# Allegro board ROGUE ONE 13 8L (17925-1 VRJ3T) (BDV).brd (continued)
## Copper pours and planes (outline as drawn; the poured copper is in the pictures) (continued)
3D3V_S0 on BOTTOM: 73.7,22.24 73.57,22.37 73.57,22.88 73.45,23.01 72.81,23.01 72.68,23.13 72.68,24.28 72.81,24.4 72.81,24.66 73.7,25.55 76.49,25.55 76.87,25.16 76.87,23.64 76.75,23.51 75.6,23.51 75.35,23.26 75.35,22.37 75.22,22.24
3D3V_S0 on BOTTOM: 166.03,38.88 165.9,39.01 165.9,39.64 166.03,39.77 166.66,39.77 166.92,40.02 166.92,40.79 167.17,40.79 167.17,39.77 167.3,39.64 167.3,39.26 166.92,38.88
3D3V_S0 on BOTTOM: 187.36,89.17 187.01,89.53 186.53,89.53 186.35,89.71 186.35,91.2 186.48,91.33 187.24,91.33 187.36,91.46 188.51,91.46 188.63,91.33 188.63,89.81 188,89.17 ; 1 cut-out
3D3V_S0 on L3SGND: 190.16,5.99 189.02,4.84 185.08,4.84 183.43,6.5 181.14,6.5 176.95,2.3 163.11,2.3 161.84,3.57 160.06,3.57 159.04,2.56 143.04,2.56 142.28,3.32 142.28,6.37 144.06,8.15 170.6,8.15 170.98,8.53 178.86,8.53 179.36,9.04 183.55,9.04 184.32,9.8 187.24,9.8 190.16,6.88 ; 1 cut-out
3D3V_S0 on L3SGND: 182.54,66.82 181.01,66.82 179.62,65.42 179.62,64.41 180,64.03 181.01,64.03 182.67,65.68 182.67,66.69
3D3V_S0 on L3SGND: 141.77,102.51 141.77,100.98 145.07,97.68 145.58,97.68 152.19,91.08 155.61,91.08 159.93,86.76 159.93,85.49 160.44,84.98 161.08,84.98 161.58,85.49 161.58,86 162.09,86.51 162.09,88.41 156.76,93.74 152.19,93.74 145.33,100.6 145.33,102 144.57,102.76 142.03,102.76
3D3V_S0 on L3SGND: 144.44,21.86 145.96,21.86 147.74,23.64 147.74,24.02 148.25,24.53 155.23,24.53 159.68,28.97 159.68,36.98 161.35,38.65 161.35,39.16 161.25,39.26 160.57,39.26 160.44,39.39 160.44,40.28 161.84,41.67 161.84,48.02 167.55,53.74 167.55,57.93 170.98,61.36 172.25,61.36 173.39,62.5 173.39,64.66 173.01,65.04 169.97,65.04 166.41,61.49 166.41,60.6 164.25,58.44 164.25,55.01 161.27,52.02 159.11,52.02 156.63,49.55 156.63,32.28 156.12,31.77 156.12,28.59 155.49,27.96 148.88,27.96 143.93,23.01 143.93,22.37 ; 1 cut-out
3D3V_S0 on L4SGND: 160.72,39.26 165.44,39.26 165.95,39.77 166.43,39.77 166.64,39.57 166.64,38.91 165.85,38.12 160.92,38.12 160.54,38.5 160.54,39.08
3D3V_S0 on L4SGND: 72.43,26.56 72.43,24.53 73.45,23.51 73.45,22.37 74.08,21.74 81.19,21.74 82.08,22.62 96.18,22.62 96.81,23.26 100.24,23.26 103.8,19.7 110.66,19.7 111.93,20.97 122.85,20.97 123.23,20.59 129.07,20.59 130.09,21.61 130.09,23.26 125.13,28.21 74.08,28.21
3D3V_S0 on L4SGND: 171.74,65.42 171.36,65.04 171.36,63.65 172.12,62.88 180.51,62.88 181.78,64.15 181.78,65.68 181.52,65.93 179.87,65.93 179.36,65.42
3D3V_S5 on TOP: 31.28,18.43 30.82,18.89 30.82,21.2 30.98,21.35 32.04,21.35 32.17,21.23 32.17,18.81 31.79,18.43
3D3V_S5 on TOP: 77.76,4.08 72.18,9.67 72.18,17.67 72.56,18.05 72.56,19.7 72.94,20.08 72.94,20.72 73.06,20.85 74.59,20.85 75.1,20.34 75.1,13.48 76.49,12.08 76.49,10.81 76.75,10.56 79.03,10.56 79.41,10.18 79.41,8.65 80.56,7.51 81.32,7.51 81.83,7 91.86,7 92.37,7.51 94.27,7.51 94.78,8.02 108.75,8.02 110.02,9.29 110.02,11.32 109.51,11.83 109.51,21.99 112.05,24.53 115.74,24.53 116.12,24.15 116.12,22.5 115.86,22.24 115.86,21.74 115.61,21.48 113.96,21.48 112.56,20.08 112.56,11.98 113.13,11.41 128.08,11.41 131.04,8.45 133.59,8.45 134.28,7.77 134.28,5.17 133.8,4.69 130.24,4.69 127.03,7.9 114.83,7.9 111.01,4.08 ; 16 cut-outs
3D3V_S5 on TOP: 170.98,49.17 170.6,49.55 170.6,56.79 173.52,59.71 173.52,64.92 173.14,65.3 169.2,65.3 168.82,65.68 168.82,66.95 168.95,67.07 170.22,67.07 170.73,67.58 171.36,67.58 171.36,66.95 171.49,66.82 172.25,66.82 172.38,66.95 172.38,68.47 172.51,68.6 173.27,68.6 173.52,68.34 175.05,68.34 175.3,68.6 176.7,68.6 176.82,68.47 177.08,68.47 177.2,68.34 177.2,66.82 176.57,66.19 176.57,64.92 175.3,63.65 175.3,58.57 172.63,55.9 172.63,49.68 172.12,49.17 ; 4 cut-outs
3D3V_S5 on BOTTOM: 28.44,91.94 27.19,93.19 24.47,93.19 24.3,93.36 24.3,94.63 24.8,95.14 26.84,95.14 27.1,94.88 29.11,94.88 29.38,95.14 30.77,95.14 32.81,97.17 32.81,99.71 35.09,102 47.03,102 49.06,104.03 73.7,104.03 75.1,102.63 76.49,102.63 77.51,103.65 78.27,103.65 78.65,103.27 78.65,102.13 78.14,101.62 77.76,101.62 77.13,100.98 73.95,100.98 73.7,101.24 53.25,101.24 53.13,101.36 52.36,101.36 52.11,101.62 50.46,101.62 48.93,100.09 47.28,100.09 46.27,99.08 37.12,99.08 29.99,91.94 ; 4 cut-outs
3D3V_S5 on BOTTOM: 73.45,16.66 73.06,17.04 73.06,17.8 72.68,18.18 72.68,21.74 73.83,21.74 73.95,21.86 74.97,21.86 75.1,21.74 75.1,17.29 74.46,16.66
3D3V_S5 on BOTTOM: 170.98,66.19 170.6,66.57 170.6,67.46 170.98,67.84 172.76,67.84 173.01,68.09 173.27,68.09 173.52,67.84 173.52,67.2 172.51,66.19
3D3V_S5 on BOTTOM: 115.61,21.61 114.47,22.75 113.83,22.75 113.45,22.37 110.78,22.37 110.78,22.88 111.42,22.88 111.67,23.13 111.67,24.02 113.07,24.02 113.45,24.4 113.45,27.32 116.5,27.32 116.5,23.26 116.37,23.13 116.37,21.74 116.24,21.61 ; 1 cut-out
3D3V_S5 on BOTTOM: 171.74,1.67 171.62,1.8 171.62,2.94 171.11,3.45 168.44,3.45 168.31,3.57 168.31,6.5 172,6.5 172.25,6.24 172.25,4.84 173.01,4.08 174.03,4.08 174.16,3.96 174.16,2.3 173.52,1.67 ; 2 cut-outs
3D3V_S5 on BOTTOM: 157.01,70.76 156.88,70.88 156.88,71.54 157.82,72.48 158.18,72.48 158.33,72.64 158.33,73.6 158.26,73.68 157.77,73.68 157.52,73.93 157.52,74.82 157.65,74.95 159.88,74.95 160.57,74.26 160.57,71.21 160.36,71.01 158.54,71.01 158.28,70.76 ; 3 cut-outs
3D3V_S5 on BOTTOM: 45.12,20.34 44.74,20.72 44.74,23.26 45.12,23.64 45.12,25.42 45,25.55 43.55,25.55 43.22,25.21 43.22,25.01 43.02,24.81 42.53,24.81 42.46,24.88 42.46,25.6 43.17,26.31 45.89,26.31 46.14,26.05 46.14,23.01 46.01,22.88 46.01,20.8 45.91,20.69 45.76,20.69 45.4,20.34 ; 3 cut-outs
3D3V_S5 on L3SGND: 31.15,9.8 31.03,9.8 29.12,11.7 21.38,11.7 20.74,11.07 19.85,11.07 16.93,13.99 16.93,23.01 14.14,25.8 14.14,35.71 14.01,35.83 14.01,36.72 17.82,40.53 17.82,46.25 19.98,48.41 19.98,50.82 16.17,54.63 16.17,64.41 17.57,65.8 18.58,65.8 20.74,67.96 20.74,73.04 22.52,74.82 23.79,74.82 24.3,75.33 24.3,82.44 26.46,84.6 26.46,90.06 23.79,92.73 23.79,94 24.8,95.01 25.95,95.01 28.11,92.86 28.11,75.58 25.69,73.17 25.69,72.28 24.04,70.63 24.04,65.55 22.39,63.9 19.72,63.9 18.71,62.88 18.71,62.12 18.84,61.99 18.84,57.42 23.53,52.72 23.53,35.45 26.58,32.4 26.58,27.45 27.85,27.45 29.12,28.72 36.11,28.72 37.89,26.94 37.89,22.12 37.25,21.48 37.25,18.43 38.14,17.54 44.11,17.54 44.36,17.8 44.36,20.47 45.25,21.35 45.63,21.35 45.89,21.1 45.89,17.04 51.86,11.07 67.35,11.07 71.03,14.75 71.03,18.94 72.43,20.34 74.21,20.34 75.1,19.45 75.1,10.31 71.16,6.37 43.09,6.37 42.46,7 33.95,7
3D3V_S5 on L3SGND: 134.18,8.25 130.9,8.25 130.44,7.79 130.44,5.12 130.93,4.64 136.61,4.64 144.95,12.97 149.14,12.97 150.15,13.99 151.17,13.99 151.8,14.62 157.27,14.62 168.44,25.8 168.44,27.58 173.9,33.04 173.9,42.94 174.41,43.45 174.41,47.77 172.89,49.29 172.89,50.06 172.12,50.82 171.36,50.82 170.47,49.93 170.47,48.02 171.87,46.63 171.87,44.98 171.74,44.85 171.74,41.17 171.24,40.66 171.24,38.88 170.47,38.88 170.35,39.01 170.17,39.01 169.76,39.41 168.31,39.41 168.19,39.29 168.19,34.31 164.76,30.88 164.76,26.56 156.63,18.43 147.49,18.43 146.6,17.54 143.47,17.54
3D3V_S5 on L4SGND: 136.69,5.73 137.2,5.23 156.88,5.23 157.39,5.73 171.36,5.73 173.78,3.32 173.78,2.53 173.29,2.05 172.12,2.05 171.11,3.07 165.27,3.07 164.5,2.3 132.75,2.3 130.34,4.72 130.34,5.35 130.72,5.73
3D3V_S5 on L4SGND: 175.55,72.54 175.68,72.66 181.78,72.66 183.68,70.76 183.68,70.25 183.3,69.87 179.36,69.87 177.84,71.39 177.33,71.39 176.82,70.88 176.82,68.09 176.06,67.33 172.76,67.33 169.58,70.5 162.73,70.5 161.2,72.03 158.41,72.03 158.03,72.41 158.03,73.81 158.41,74.19 161.96,74.19 163.62,72.54
3D3V_S5_KBC on TOP: 37.25,2.94 35.85,4.34 35.85,5.48 35.75,5.58 35.22,5.58 34.51,6.29 34.51,7.33 34.63,7.46 35.17,7.46 35.35,7.28 35.35,6.29 35.55,6.09 36.89,6.09 38.39,4.59 56.43,4.59 56.58,4.44 56.58,3.04 56.48,2.94 ; 2 cut-outs
3D3V_S5_KBC on TOP: 32.81,27.2 32.68,27.32 32.68,27.7 33.03,28.06 33.03,28.77 32.93,28.87 32.93,30.8 33.08,30.96 33.97,30.96 34.15,30.78 34.15,27.53 33.82,27.2 ; 3 cut-outs
3D3V_S5_KBC on TOP: 9.36,21.15 9.23,21.28 9.23,24.4 9.31,24.48 9.67,24.48 9.74,24.4 9.74,21.68 9.84,21.58 10.43,21.58 10.5,21.66 10.5,22.01 10.55,22.07 11.42,22.07 12.1,22.75 14.26,22.75 14.52,22.5 14.52,21.86 14.39,21.74 13.63,21.74 13.5,21.61 11.67,21.61 11.22,21.15
3D3V_S5_PCH on TOP: 143.3,71.77 142.3,72.76 140.96,72.76 140.83,72.89 140.83,73.73 141.29,74.19 141.29,74.49 141.59,74.8 151.25,74.8 151.26,74.78 151.42,74.95 151.93,74.95 153.46,76.47 157.14,76.47 157.39,76.22 157.39,75.33 157.27,75.2 153.96,75.2 152.44,73.68 152.44,72.28 151.93,71.77 ; 1 cut-out
3D3V_S5_PCH on TOP: 140.5,82.77 140.35,82.92 140.35,85.24 140.02,85.57 140.02,86.25 140.09,86.33 140.5,86.33 141.49,85.34 141.49,83.2 141.06,82.77
3D3V_S5_PCH on TOP: 141.77,79.16 141.64,79.29 140.45,79.29 140.17,79.57 138.6,79.57 138.57,79.6 138.57,81.76 138.6,81.78 139.94,81.78 140.42,81.3 140.42,80.23 140.53,80.13 145.61,80.13 145.73,80 145.73,79.29 145.61,79.16 ; 2 cut-outs
3D3V_S5_PCH on BOTTOM: 155.61,73.81 155.49,73.93 155.49,75.08 157.01,76.6 159.55,76.6 159.81,76.35 159.81,75.71 159.3,75.2 157.65,75.2 157.27,74.82 157.27,74.06 157.01,73.81 ; 1 cut-out
3D3V_SEN_S0 on TOP: 121.32,97.43 121.2,97.55 121.2,101.24 121.32,101.36 124.12,101.36 124.25,101.24 124.25,100.73 122.21,98.7 122.21,97.55 122.09,97.43 ; 4 cut-outs
3D3V_SEN_S0 on BOTTOM: 121.45,95.27 121.2,95.52 121.2,97.94 121.32,98.06 121.83,98.06 122.09,97.81 122.09,95.4 121.96,95.27
3D3V_SSD on TOP: 190.79,15.64 190.54,15.89 190.54,16.4 191.81,17.67 191.81,19.07 191.68,19.2 191.56,19.2 191.43,19.32 191.43,21.23 191.05,21.61 191.05,22.62 191.3,22.88 193.71,22.88 194.35,22.24 194.35,16.53 193.46,15.64 ; 8 cut-outs
3D3V_SSD on TOP: 193.08,4.34 192.57,4.84 192.57,6.11 192.44,6.24 191.81,6.24 191.68,6.37 191.68,9.92 191.81,10.05 193.84,10.05 194.48,9.42 194.48,4.84 193.97,4.34 ; 5 cut-outs
3D3V_SSD on BOTTOM: 193.18,4.21 191.17,6.22 191.17,21.23 192.57,22.62 195.37,22.62 195.37,21.74 194.35,21.74 194.35,20.08 195.24,20.08 195.24,18.18 194.35,18.18 193.21,17.04 193.21,6.75 194.35,5.61 195.24,5.61 195.24,4.21
3D3V_TP_VDD on TOP: 81.95,7.21 81.09,8.07 81.09,9.59 80.79,9.9 80.79,10.66 80.99,10.86 82.18,10.86 82.31,10.99 82.31,11.96 82.49,12.13 82.87,12.13 83.1,11.91 83.1,9.19 83.22,9.06 84.8,9.06 84.82,9.04 84.82,8.1 84.62,7.89 84.09,7.89 84.06,7.87 84.06,7.33 83.94,7.21 ; 4 cut-outs
3D3V_TPAN_VDD on TOP: 131.23,97.55 131.1,97.68 131.1,99.33 132.25,100.48 133.01,100.48 133.14,100.6 139.87,100.6 140.12,100.35 140.12,99.33 139.99,99.21 132.37,99.21 132.25,99.08 132.25,98.06 131.74,97.55 ; 6 cut-outs
3D3V_TPAN_VDD on BOTTOM: 131.36,95.27 131.23,95.4 131.23,97.94 131.36,98.06 131.74,98.06 131.87,97.94 131.87,95.4 131.74,95.27
3D3V_TPM_VSB on TOP: 186.48,45.23 186.35,45.36 186.35,45.74 186.22,45.87 185.59,45.87 184.44,47.01 184.44,47.52 187.11,47.52 187.24,47.39 187.24,45.23 ; 1 cut-out
3D3V_VCCDSW on BOTTOM: 127.32,60.01 127.19,60.14 127.19,61.08 129.63,61.08 129.76,60.95 129.76,60.37 129.4,60.01
3D3V_VCCPRIM on TOP: 139.59,70.48 139.46,70.6 138.82,70.6 138.57,70.86 138.57,72.26 138.44,72.38 135.45,72.38 134.99,72.84 131.18,72.84 130.21,73.81 130.21,73.82 129.83,74.2 127.05,74.2 126.53,74.72 126.53,75.2 127.29,75.96 127.67,75.96 128.31,75.33 131.61,75.33 131.99,75.71 133.01,75.71 133.14,75.58 133.14,75.33 133.9,74.57 133.9,74.16 133.95,74.11 134.96,74.11 135.28,73.79 135.61,73.79 136.26,73.14 138.75,73.14 139.54,73.93 140.45,73.93 140.69,73.69 140.69,72.83 140.6,72.74 139.56,72.74 139.43,72.61 139.43,71.57 140.09,70.91 140.09,70.58 139.99,70.48 ; 8 cut-outs
3D3V_VCCPRIM on BOTTOM: 131.61,74.19 131.48,74.31 131.48,75.33 131.61,75.46 133.01,75.46 133.14,75.33 133.14,74.31 133.01,74.19
3D3V_WLAN on TOP: 170.73,61.61 170.22,62.12 167.93,62.12 167.81,62.25 167.81,62.38 166.79,63.39 166.41,63.39 166.28,63.52 166.28,64.03 166.41,64.15 167.3,64.15 167.93,64.79 170.98,64.79 171.49,64.28 171.49,61.74 171.36,61.61 ; 3 cut-outs
3D3V_WLAN on BOTTOM: 165.01,44.85 164.76,45.1 164.76,45.99 165.77,45.99 167.81,48.02 167.81,48.66 168.19,49.04 168.19,54.63 167.81,55.01 167.81,57.55 168.95,58.69 169.58,58.69 169.97,59.07 169.97,60.6 169.58,60.98 168.82,60.98 167.81,61.99 167.81,62.63 164.63,62.63 164.38,62.88 164.38,63.52 164.63,63.77 165.9,63.77 167.3,65.17 167.3,67.58 167.43,67.71 168.31,67.71 168.7,68.09 169.33,68.09 169.46,67.96 169.46,66.57 170.35,65.68 170.98,65.68 172.12,64.53 172.12,55.52 170.73,54.12 170.73,48.02 170.35,47.64 170.35,47.39 167.81,44.85 ; 2 cut-outs
+DC_IN_C on TOP: 39.92,87.52 39.92,89.68 40.81,90.57 40.81,91.84 41.31,92.35 45.51,92.35 46.01,91.84 46.01,90.06 43.47,87.52 ; 3 cut-outs
+DC_IN_C on BOTTOM: 40.17,87.52 40.04,87.65 40.04,89.3 40.43,89.3 40.81,89.68 40.81,91.97 41.19,92.35 46.01,92.35 47.79,90.57 47.79,89.17 47.66,89.05 45.76,89.05 44.62,87.9 41.57,87.9 41.19,87.52
+SDC_IN on TOP: 20.99,56.66 20.61,57.04 20.61,59.84 21.25,59.84 21.5,60.09 21.5,60.47 21.63,60.6 22.9,60.6 23.28,60.98 36.16,60.98 36.34,61.16 36.34,71.44 36.31,71.47 35.78,71.47 35.35,71.9 35.35,77.74 35.73,78.12 35.73,78.38 37.12,79.77 39.03,79.77 40.17,78.63 40.17,74.95 39.92,74.69 39.92,72.41 40.93,71.39 40.93,66.44 41.31,66.06 41.31,64.28 42.71,62.88 42.71,61.87 40.3,59.45 40.27,59.45 38.6,57.78 36.28,57.78 35.55,57.04 33.44,57.04 33.06,56.66 ; 2 cut-outs
+SDC_IN on BOTTOM: 38.52,74.44 38.39,74.57 38.39,75.58 38.01,75.96 38.01,77.74 37.76,78 37,78 36.74,78.25 36.74,79.52 36.87,79.65 37.25,79.65 37.38,79.77 37.38,80.66 39.54,80.66 39.79,80.41 39.79,78 39.28,77.49 39.28,74.57 39.16,74.44 ; 3 cut-outs
+SDC_IN on BOTTOM: 41.31,61.11 41.06,61.36 39.79,61.36 39.66,61.49 39.66,63.9 40.17,64.41 41.31,64.41 43.47,62.25 43.47,61.36 43.22,61.11
AUD_AGND on L2SGND: 180.3,39.82 180.94,39.18 181.47,39.18 181.78,38.88 181.78,32.38 183.22,30.93 183.22,14.8 180.96,12.54 177.79,12.54 177.53,12.79 177.53,14.45 176.77,15.21 176.77,16.71 178.04,16.71 178.3,16.96 178.3,21.53 177.89,21.94 176.26,21.94 176.26,26 176.65,26.38 176.65,28.67 174.99,30.32 174.99,40.58 175.25,40.84 180.18,40.84 180.3,40.71
AUD_AGND on L5GND, L7GND: 177.79,12.53 177.52,12.8 177.52,14.45 176.76,15.21 176.76,16.72 178.05,16.72 178.28,16.96 178.28,21.56 177.92,21.93 176.25,21.93 176.25,25.97 176.63,26.36 176.63,28.67 174.98,30.32 174.98,40.58 175.25,40.85 180.17,40.85 180.32,40.71 180.32,39.82 180.96,39.17 181.47,39.17 181.76,38.88 181.76,32.4 183.24,30.93 183.24,14.83 180.94,12.53
AUD_RING on TOP: 175.1,34.79 175.05,34.84 175.05,36.75 175.2,36.9 176.01,36.9 176.06,36.85 176.06,34.94 175.91,34.79
AUD_SELEEVE on TOP: 180.76,35.17 180.66,35.27 180.66,37 180.79,37.13 181.6,37.13 181.65,37.08 181.65,35.27 181.55,35.17
AUD_SPK_L+ on TOP: 18.56,4.44 17.69,5.3 17.69,6.62 19.47,6.62 20.36,5.73 20.36,4.59 20.21,4.44 ; 3 cut-outs
AUD_SPK_L+ on BOTTOM: 176.52,13.71 175.78,14.45 175.78,16.6 175.81,16.63 175.96,16.63 175.98,16.6 175.98,14.9 176.24,14.65 176.8,14.65 177.13,14.32 177.13,13.91 176.92,13.71
AUD_SPK_L+_C on TOP: 17.69,6.88 17.57,7 17.57,9.67 16.8,10.43 16.8,11.07 17.06,11.32 17.82,11.32 19.09,10.05 19.09,7.13 18.84,6.88 ; 1 cut-out
AUD_SPK_L- on TOP: 16.78,3.7 16.42,4.06 16.42,5.23 16.17,5.48 16.17,6.62 17.31,6.62 17.44,6.5 17.44,5.35 17.82,4.97 17.82,3.83 17.69,3.7 ; 1 cut-out
AUD_SPK_L- on BOTTOM: 175.5,12.9 175.27,13.12 175.27,14.09 175.38,14.19 175.38,16.6 175.43,16.66 175.53,16.66 175.58,16.6 175.58,14.39 176.09,13.89 176.09,13.07 175.91,12.9
AUD_SPK_L-_C on TOP: 16.17,6.88 16.17,8.65 15.53,9.29 15.53,11.58 15.79,11.83 16.42,11.83 16.68,11.58 16.68,10.31 17.31,9.67 17.31,7 17.18,6.88
AUD_SPK_R+ on TOP: 14.14,3.83 13.88,4.08 13.88,5.99 14.14,6.24 14.26,6.24 14.77,6.75 15.91,6.75 15.91,5.61 15.79,5.48 15.28,5.48 15.28,4.72 15.15,4.59 15.03,4.59 15.03,4.08 14.77,3.83 ; 3 cut-outs
AUD_SPK_R+ on BOTTOM: 173.75,14.09 173.6,14.24 173.6,14.75 173.8,14.95 174.16,14.95 174.59,15.39 174.59,16.76 174.79,16.55 174.79,14.75 174.13,14.09
AUD_SPK_R+_C on TOP: 14.9,6.88 14.26,7.51 14.26,11.19 14.39,11.32 15.15,11.32 15.28,11.19 15.28,10.94 15.41,10.81 15.41,9.16 15.91,8.65 15.91,6.88 ; 1 cut-out
AUD_SPK_R- on TOP: 12.26,3.83 11.85,4.23 11.85,5.23 12.23,5.61 13.63,5.61 13.76,5.48 13.76,4.08 13.5,3.83 ; 1 cut-out
AUD_SPK_R- on BOTTOM: 174.23,13.07 174.08,13.23 174.08,13.78 174.97,14.67 174.97,16.63 175.17,16.63 175.2,16.6 175.2,14.29 175.1,14.19 175.1,13.4 174.77,13.07
AUD_SPK_R-_C on TOP: 12.74,5.86 12.74,11.32 13.12,11.7 13.76,11.7 13.88,11.58 13.88,6.37 13.76,6.24 13.76,5.86
BT+ on TOP: 105.2,14.12 104.31,15 104.31,16.27 105.2,17.16 106.59,17.16 107.74,16.02 107.74,14.75 107.1,14.12
BT+ on BOTTOM: 99.23,8.15 98.08,9.29 98.08,12.59 98.21,12.72 101.51,12.72 101.77,12.97 102.78,12.97 104.05,14.24 104.05,18.31 104.81,19.07 109.51,19.07 110.02,18.56 110.02,16.91 110.53,16.4 110.53,10.56 108.12,8.15 ; 4 cut-outs
DCBATOUT on TOP: outline of 198 points within 39.28,20.34 177.59,105.17 ; 59 cut-outs
DCBATOUT on BOTTOM: 56.55,90.82 55.51,91.86 55.51,99.43 55.92,99.84 70.22,99.84 70.24,99.81 70.68,99.81 73.06,97.43 74.72,97.43 74.72,93.87 72.02,93.87 70.14,95.75 70.14,97.99 69.94,98.19 61.51,98.19 61.49,98.18 59.67,98.18 59.6,98.11 59.6,91.84 59.35,91.59 57.95,91.59 57.19,90.82
DCBATOUT on BOTTOM: 164.25,67.71 164,67.96 164,70.63 164.25,70.88 166.16,70.88 166.28,70.76 166.28,68.6 165.39,67.71
DCBATOUT on BOTTOM: 168.7,103.14 168.57,103.27 168.57,104.92 168.82,105.17 170.6,105.17 170.85,104.92 170.85,104.41 171.11,104.41 171.24,104.29 171.24,103.65 170.73,103.14 ; 1 cut-out
DCBATOUT on BOTTOM: 59.22,70.5 58.84,70.88 58.84,73.04 59.48,73.68 60.75,73.68 60.87,73.55 60.87,70.63 60.75,70.5
DCBATOUT on BOTTOM: 97.96,17.67 97.83,17.8 97.83,20.72 97.7,20.85 97.7,24.53 100.12,24.53 100.24,24.4 100.75,24.4 102.02,23.13 102.02,17.8 101.89,17.67 ; 2 cut-outs
DCBATOUT on BOTTOM: 80.94,23.51 80.43,24.02 80.43,24.4 80.18,24.66 79.8,24.66 79.54,24.91 79.54,25.29 78.91,25.93 71.16,25.93 70.78,25.55 64.17,25.55 64.05,25.42 48.3,25.42 45.51,28.21 45.51,33.42 45.12,33.8 45.12,36.98 45,37.1 45,37.36 45.51,37.86 45.51,38.88 45,39.39 45,39.64 44.49,40.15 39.79,40.15 38.65,39.01 38.01,39.01 37.89,39.13 37.89,40.15 37.5,40.53 37.5,41.17 39.41,43.07 41.44,43.07 41.7,43.33 41.7,49.42 44.74,52.47 44.74,53.1 45.51,53.87 46.27,53.87 46.52,54.12 47.92,54.12 48.43,54.63 48.43,55.01 48.68,55.26 49.57,55.26 49.57,52.72 49.32,52.47 48.55,52.47 47.66,51.58 47.66,29.48 49.95,27.2 79.92,27.2 82.21,24.91 86.91,24.91 87.03,24.78 87.03,23.77 86.78,23.51 ; 9 cut-outs
JGND on TOP: 37.5,87.01 37,87.52 37,89.55 37.5,90.06 39.28,90.06 39.66,89.68 39.66,87.52 39.16,87.01 ; 4 cut-outs
JGND on BOTTOM: 36.23,85.87 35.98,86.12 35.98,91.08 36.11,91.2 38.52,91.2 38.77,90.95 38.77,89.55 38.9,89.43 39.28,89.43 39.41,89.3 39.41,87.39 39.28,87.27 38.77,87.27 38.19,86.68 38.19,86.15 37.91,85.87
PWR_1D0V_PH on BOTTOM: 170.5,74.24 170.4,74.34 169.89,74.34 169.89,75.05 169.97,75.13 170.37,75.13 170.45,75.05 172.66,75.05 172.73,75.13 172.73,78.53 173.52,79.32 177.79,79.32 177.97,79.14 177.97,76.09 176.75,74.87 173.65,74.87 173.52,74.74 173.52,74.36 173.39,74.24 ; 2 cut-outs
PWR_2D5V on BOTTOM: 116.6,23.44 116.6,25.47 116.73,25.6 120.16,25.6 120.54,25.98 121.55,25.98 122.06,26.48 122.95,26.48 123.08,26.36 123.08,24.83 123.1,24.81 123.1,24.53 122.01,23.44 ; 8 cut-outs
PWR_3D3V on BOTTOM: 75.22,16.4 75.1,16.53 75.1,21.74 75.22,21.86 75.86,21.86 75.99,21.74 80.43,21.74 80.81,22.12 82.84,22.12 83.35,21.61 83.35,17.93 81.83,16.4 ; 14 cut-outs
PWR_3D3V_LDO on BOTTOM: 88.94,15.64 88.94,19.7 89.45,20.21 90.34,20.21 90.34,19.83 89.83,19.32 89.83,15.77 89.7,15.64
PWR_3D3V_PH on BOTTOM: 86.02,17.93 85.89,18.05 85.89,22.12 86.91,23.13 89.19,23.13 89.96,22.37 89.96,21.74 90.34,21.35 90.34,20.85 88.94,20.85 88.69,20.59 88.69,17.93
PWR_5V on BOTTOM: 62.14,15 61,16.15 61,21.1 61.63,21.74 69.13,21.74 69.13,15 ; 18 cut-outs
PWR_5V_PH on BOTTOM: 54.78,16.15 54.4,16.53 54.4,17.29 54.01,17.67 54.01,18.05 55.16,18.05 55.67,18.56 55.67,20.08 55.79,20.21 58.46,20.21 58.59,20.08 58.59,16.66 58.08,16.15
PWR_5V_VCC on BOTTOM: 54.01,18.81 54.01,19.2 54.78,19.96 54.78,20.97 55.41,21.61 55.41,23.01 55.54,23.13 56.17,23.13 56.3,23.01 56.3,21.35 55.54,20.59 55.54,19.45 54.9,18.81
PWR_CHG_HG1_R on TOP: 41.92,50.51 41.82,50.61 41.82,52.57 41.9,52.65 42.89,52.65 43.22,52.98 44.36,52.98 44.62,52.72 44.62,51.76 44.51,51.66 43.52,51.66 42.38,50.51
PWR_CHG_HG2_R on TOP: 39.26,41.55 39.21,41.6 39.21,43.02 39.33,43.15 39.92,43.15 40.49,43.72 40.49,44.28 40.55,44.34 41.19,44.34 41.31,44.21 41.31,43.45 41.06,43.2 41.06,41.67 40.93,41.55
PWR_CHG_PHASE1 on TOP: 37.12,49.8 36.49,50.44 36.49,55.29 36.59,55.39 37.63,55.39 37.89,55.64 37.89,57.17 38.01,57.3 38.9,57.3 39.03,57.17 39.03,53.13 39.56,52.6 41.52,52.6 41.59,52.52 41.59,50.08 41.31,49.8
PWR_CHG_PHASE1 on BOTTOM: 37.12,49.8 36.49,50.44 36.49,55.26 36.62,55.39 41.19,55.39 41.62,54.96 41.62,50.11 41.31,49.8
PWR_CHG_PHASE2 on TOP: 37.38,43.33 37.25,43.45 37.25,48.53 37.5,48.79 41.19,48.79 41.44,48.53 41.44,44.72 41.31,44.6 40.43,44.6 39.79,43.96 39.79,43.45 39.66,43.33
PWR_CHG_PHASE2 on BOTTOM: 37.35,43.38 37.17,43.55 37.17,48.56 37.38,48.76 41.09,48.76 41.47,48.38 41.47,43.63 41.21,43.38
PWR_CHG_VBATIN on BOTTOM: 98.08,12.97 97.7,13.35 97.7,16.91 97.96,17.16 102.02,17.16 102.02,15.89 101.77,15.64 101.77,14.5 101.26,13.99 100.62,13.99 100.5,13.86 100.5,13.23 100.24,12.97
PWR_DCBATOUT_1D0V on TOP: 169.58,72.15 169.2,72.54 169.2,74.19 169.58,74.57 173.39,74.57 173.52,74.44 173.52,72.66 173.01,72.15
PWR_DCBATOUT_1D0V on BOTTOM: 169.97,70.63 169.84,70.76 169.84,71.01 169.46,71.39 168.57,71.39 168.31,71.14 164.25,71.14 164.25,74.31 164.38,74.44 165.9,74.44 166.03,74.31 169.46,74.31 169.84,73.93 173.27,73.93 173.52,73.68 173.52,72.41 170.6,72.41 170.47,72.28 170.47,70.76 170.35,70.63 ; 2 cut-outs
PWR_DCBATOUT_3D3V on BOTTOM: 94.15,21.35 93.64,21.86 92.37,21.86 91.99,21.48 90.72,21.48 90.59,21.61 90.59,24.53 90.72,24.66 97.32,24.66 97.45,24.53 97.45,21.48 97.32,21.35 ; 1 cut-out
PWR_DCBATOUT_5V on TOP: 45.3,14.5 44.11,15.69 44.11,20.47 44.49,20.85 44.49,22.88 44.62,23.01 49.42,23.01 49.58,22.84 49.58,19.61 49.09,19.12 47.99,19.12 47.77,18.89 47.77,17.44 47.99,17.21 49.9,17.21 50.59,16.53 50.59,15.26 49.82,14.5
PWR_DCBATOUT_5V on BOTTOM: 48.17,14.5 47.66,15 47.66,17.16 51.86,17.16 52.24,17.54 53.76,17.54 53.76,15.51 53.13,14.88 51.73,14.88 51.35,14.5 ; 2 cut-outs
PWR_DCBATOUT_VCCGTA on TOP: 62.78,78.25 62.14,78.89 62.14,79.65 60.75,81.04 60.75,94.13 61.63,95.01 63.03,95.01 63.67,94.38 63.67,93.11 63.79,92.98 63.79,91.71 63.41,91.33 63.41,86.25 62.9,85.74 62.9,84.22 63.16,84.22 63.79,83.58 63.79,78.63 63.41,78.25 ; 10 cut-outs
PWR_DCBATOUT_VCCGTA on BOTTOM: 62.4,78.12 62.4,79.52 62.14,79.77 61.38,79.77 61.38,80.28 60.87,80.79 59.09,80.79 58.71,81.17 58.71,84.09 58.97,84.35 62.9,84.35 63.67,83.58 63.67,82.31 63.79,82.19 63.79,81.12 63.56,80.89 63.56,78.15 63.54,78.12 ; 4 cut-outs
PWR_DCBATOUT_VCCGTA on BOTTOM: 62.4,88.54 62.27,88.66 62.27,90.06 62.14,90.19 61.38,90.19 59.98,91.59 59.98,97.53 60.39,97.94 63.92,97.94 64.17,97.68 64.17,95.4 63.79,95.01 63.79,92.86 63.64,92.7 63.64,91.66 63.56,91.59 63.56,88.56 63.54,88.54 ; 3 cut-outs
PWR_DCBATOUT_VCCGTA on L3SGND: 63.16,94.38 61.25,94.38 60.75,93.87 60.75,79.39 62.02,78.12 63.29,78.12 63.54,78.38 63.54,94
PWR_DCBATOUT_VCCGTA on L4SGND: 61.76,83.71 63.03,83.71 63.41,83.33 63.41,78.25 63.16,78 62.02,78 61.13,78.89 61.13,83.08
PWR_DCBATOUT_VCCGTA on L4SGND: 61.89,94 62.9,94 63.41,93.49 63.41,88.79 63.16,88.54 62.78,88.54 60.49,90.82 60.49,92.6
PWR_DCBATOUT_VCCGTA on L6: 61.51,93.62 62.52,93.62 63.29,92.86 63.29,88.66 63.16,88.54 62.02,88.54 60.36,90.19 60.36,92.47
PWR_DCBATOUT_VCCGTA on L6: 61.76,83.71 62.9,83.71 63.41,83.2 63.41,78.12 63.16,77.87 61.89,77.87 60.75,79.01 60.75,82.7
PWR_DCBATOUT_VCCSA on TOP: 167.04,101.24 166.79,101.49 166.79,102.13 166.92,102.25 168.19,102.25 168.31,102.13 168.31,101.49 168.06,101.24
PWR_DCBATOUT_VCCSA on BOTTOM: 166.66,100.6 166.03,101.24 164,101.24 163.74,101.49 163.74,104.79 163.87,104.92 166.28,104.92 166.54,104.67 166.54,103.27 166.79,103.02 170.22,103.02 170.22,101.75 169.08,100.6 ; 2 cut-outs
PWR_DCBATOUT_VCORE on TOP: 63.03,67.71 62.65,68.09 62.65,69.87 62.08,70.44 62.08,72.98 62.4,73.3 63.92,73.3 64.43,72.79 64.43,71.77 64.68,71.52 64.68,70.76 64.43,70.5 64.17,70.5 63.67,70 63.67,68.09 63.29,67.71 ; 3 cut-outs
PWR_DCBATOUT_VCORE on BOTTOM: 62.55,67.66 62.55,69.11 62.42,69.23 61.58,69.23 61.51,69.31 61.51,69.74 61.25,70 61.25,73.42 61.63,73.81 63.67,73.81 64.43,73.04 64.43,71.9 64.68,71.65 64.68,70.76 64.56,70.63 64.07,70.63 63.69,70.25 63.69,67.66 ; 2 cut-outs
PWR_DCBATOUT_VCORE on L3SGND, L4SGND, L6: 62.02,73.04 63.16,73.04 63.67,72.54 63.67,67.96 63.29,67.58 62.52,67.58 61.51,68.6 61.51,72.54
PWR_DCBATOUT_VDDQ on BOTTOM: 53.13,50.95 51.86,52.22 51.86,52.85 51.73,52.98 50.46,52.98 50.33,52.85 49.82,52.85 49.82,55.26 50.08,55.52 53.25,55.52 55.41,53.36 56.43,53.36 57.57,54.5 57.57,55.39 57.19,55.77 57.19,57.42 57.06,57.55 55.41,57.55 55.41,58.82 57.06,58.82 57.19,58.95 57.95,58.95 58.08,58.82 58.08,58.57 58.97,57.68 58.97,56.28 59.09,56.15 59.09,54.63 58.71,54.25 58.71,52.09 57.57,50.95 ; 2 cut-outs
PWR_VCCGT_SWA on BOTTOM: 64.81,85.74 64.81,86.51 65.95,86.51 66.21,86.76 66.21,90.44 70.27,90.44 70.91,89.81 70.91,89.43 70.27,88.79 70.27,86.63 69.38,85.74
PWR_VCCGT_SWB on BOTTOM: 64.91,75.23 64.81,75.33 64.81,75.96 64.94,76.09 65.95,76.09 66.21,76.35 66.21,79.9 66.33,80.03 70.27,80.03 70.78,79.52 70.78,79.01 70.14,78.38 70.14,76.22 69.15,75.23
PWR_VCCSA_DRVH on BOTTOM: 173.01,102.13 173.01,103.27 173.14,103.4 173.78,103.4 174.03,103.14 174.03,102.25 173.9,102.13
PWR_VCCSA_DRVH on BOTTOM: 161.71,103.78 161.58,103.9 161.58,104.54 161.84,104.79 163.36,104.79 163.49,104.67 163.49,103.9 163.36,103.78
PWR_VCCSA_DRVL on BOTTOM: 165.67,96.11 165.52,96.26 165.52,98.32 165.65,98.44 166.54,98.44 166.66,98.32 166.66,96.16 166.61,96.11
PWR_VCCSA_SW on BOTTOM: 171.11,101.87 170.98,102 170.98,102.51 171.11,102.63 171.11,103.52 171.74,104.16 171.74,104.29 172.25,104.79 172.76,104.79 172.89,104.67 172.89,103.52 171.74,102.38 171.74,102 171.62,101.87 ; 1 cut-out
PWR_VCCSA_SW on BOTTOM: 162.35,97.3 162.22,97.43 162.22,98.06 161.71,98.57 159.93,98.57 159.68,98.82 159.68,103.27 159.93,103.52 163.49,103.52 163.62,103.4 163.62,100.98 163.74,100.86 165.27,100.86 165.27,97.43 165.14,97.3
PWR_VCORE_SW on BOTTOM: 64.94,64.66 64.81,64.79 64.81,65.42 64.94,65.55 66.21,65.55 66.33,65.68 66.33,69.49 66.46,69.61 70.27,69.61 70.27,65.68 69.25,64.66
PWR_VDDQ_PH on BOTTOM: 58.33,58.44 58.21,58.57 58.21,58.95 57.95,59.2 57.19,59.2 56.94,58.95 54.01,58.95 54.01,60.6 57.06,60.6 57.95,61.49 59.73,61.49 60.24,60.98 60.24,58.57 60.11,58.44
PWR_VDDQ_VLDOIN on TOP: 55.92,55.39 55.41,55.9 55.41,56.66 55.92,57.17 58.08,57.17 58.21,57.04 58.21,55.39 ; 2 cut-outs
PWR_VDDQ_VTT on TOP: 50.08,47.77 49.95,47.9 49.95,48.79 50.08,48.91 50.08,49.55 50.33,49.8 50.33,52.34 54.14,56.15 55.03,56.15 55.28,55.9 55.28,53.36 52.36,50.44 52.36,48.53 51.6,47.77 ; 5 cut-outs
PWR_VDDQ_VTT on BOTTOM: 54.01,55.26 53.76,55.52 53.76,55.9 54.52,56.66 55.41,56.66 55.54,56.53 55.54,55.77 55.03,55.26
RING2_R on TOP: 175.15,37.15 175.05,37.25 175.05,38.5 176.32,39.77 176.54,39.77 176.87,39.44 176.87,38.68 176.09,37.89 176.09,37.25 175.98,37.15
RING2_R on BOTTOM: 175.81,38.88 175.38,39.31 175.38,40.71 175.45,40.79 176.67,40.79 176.7,40.76 176.7,39.77 176.8,39.67 176.8,39.13 176.54,38.88
SLEEVE_R on TOP: 180.73,37.31 180.58,37.46 180.58,38.22 180.46,38.35 179.87,38.35 179.08,39.13 179.08,40.66 179.19,40.76 180.15,40.76 180.25,40.66 180.25,39.82 180.07,39.64 180.07,39.24 180.18,39.13 181.37,39.13 181.65,38.85 181.65,37.41 181.55,37.31
SLEEVE_R on BOTTOM: 179.36,39.01 179.21,39.16 179.08,39.16 178.35,39.9 178.35,40.71 178.42,40.79 179.69,40.79 179.69,39.85 180.1,39.44 180.1,39.36 179.74,39.01
TCH_PNL_3D3V_5V on TOP: 134.53,100.98 134.41,101.11 134.41,102 134.53,102.13 143.3,102.13 143.55,101.87 143.55,101.36 143.17,100.98
TCH_PNL_3D3V_5V on BOTTOM: 142.03,99.46 141.9,99.59 141.9,101.62 142.28,102 143.17,102 143.42,101.75 143.42,99.69 143.19,99.46 ; 1 cut-out
USB_ADT on TOP: 13.88,57.04 12.99,57.93 12.99,59.33 15.03,59.33 16.3,60.6 17.18,60.6 17.69,61.11 19.98,61.11 20.11,60.98 20.11,57.63 19.83,57.35 18.07,57.35 17.77,57.04 ; 1 cut-out

Small or netless copper shapes (teardrops, artwork), in the pictures only: 2 on BOTTOM

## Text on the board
Ref Des/Silkscreen Bottom: F5503:1.1A/24V | X2401:32.768KHZ | F6501:1.1A/6V | X1801:24MHZ
User.Comments: CR_UNNAMED2_2 | CR_UNNAMED_6
Ref Des/Silkscreen Top: X5701:27MHZ | F5701:1.1A/6V | F5502:1.1A/6V | X1802:32.768KHZ | F5504:1.1A/6V | F5501:1.1A/6V | VRJ3T | MADE IN TAIWAN | Rogue one 13 8L | 17925-1
User.28: ByImpedance:100.0_DP@_REF_L1=("5.0/4.0(L3)" "3.0/9.0(L2)")|_REF_L6=("3.0/7.5(L5/L7)" "3.5/7.0(L4/L7)")|Type="DP"|_REF_L3=("3.5/7.0(L2/L5)" "3.0/7.5(L2/L4)")|_REF_L4=("3.0/7.5(L3/L5)" "3.5/7.0(L2/L5)")|imp="100.0"|_REF_L5=("3.5/7.0(L4/L7)")|_REF_L8=("3.0/9.0(L7)" "5.0/4.0(L6)") | ByImpedance:27.4_SE@_REF_L1=("11.0(L2)")|_REF_L6=("10.5(L5/L7)" "13.5(L4/L7)")|Type="SE"|_REF_L3=("13.5(L2/L5)" "10.5(L2/L4)")|_REF_L4=("13.5(L2/L5)" "10.5(L3/L5)")|imp="27.4"|_REF_L5=("13.5(L4/L7)")|_REF_L8=("11.0(L7)") | ByImpedance:33.0_SE@_REF_L1=("8.0(L2)")|_REF_L6=("8.1(L5/L7)" "10.0(L4/L7)")|Type="SE"|_REF_L3=("10.0(L2/L5)" "8.1(L2/L4)")|_REF_L4=("10.0(L2/L5)" "8.1(L3/L5)")|imp="33.0"|_REF_L5=("10.0(L4/L7)")|_REF_L8=("8.0(L7)") | ByImpedance:35.0_SE@_REF_L1=("7.5(L2)")|_REF_L6=("7.1(L5/L7)" "9.0(L4/L7)")|Type="SE"|_REF_L3=("9.0(L2/L5)" "7.1(L2/L4)")|_REF_L4=("9.0(L2/L5)" "7.1(L3/L5)")|imp="35.0"|_REF_L5=("9.0(L4/L7)")|_REF_L8=("7.5(L7)") | ByImpedance:37.5_SE@_REF_L1=("6.5(L2)")|_REF_L6=("8.0(L4/L7)" "6.6(L5/L7)")|Type="SE"|_REF_L3=("8.0(L2/L5)" "6.6(L2/L4)")|_REF_L4=("8.0(L2/L5)" "6.6(L3/L5)")|imp="37.5"|_REF_L5=("8.0(L4/L7)")|_REF_L8=("6.5(L7)") | ByImpedance:39.0_SE@_REF_L1=("6.0(L2)")|_REF_L6=("6.1(L5/L7)" "7.5(L4/L7)")|Type="SE"|_REF_L3=("7.5(L2/L5)" "6.1(L2/L4)")|_REF_L4=("6.1(L3/L5)" "7.5(L2/L5)")|imp="39.0"|_REF_L5=("7.5(L4/L7)")|_REF_L8=("6.0(L7)") | ByImpedance:40.0_SE@_REF_L2=("3.5(L1/L3)")|_REF_L1=("5.5(L2)")|_REF_L6=("5.6(L5/L7)" "7.0(L4/L7)")|Type="SE"|_REF_L3=("7.0(L2/L5)" "5.6(L2/L4)")|_REF_L4=("5.6(L3/L5)" "7.0(L2/L5)")|imp="40.0"|_REF_L5=("7.0(L4/L7)")|_REF_L8=("5.5(L7)") | ByImpedance:42.0_SE@_REF_L1=("5.0(L2)")|_REF_L6=("6.5(L4/L7)" "5.1(L5/L7)")|Type="SE"|_REF_L3=("6.5(L2/L5)" "5.1(L2/L4)")|_REF_L4=("5.1(L3/L5)" "6.5(L2/L5)")|imp="42.0"|_REF_L5=("6.5(L4/L7)")|_REF_L8=("5.0(L7)") | ByImpedance:45.0_SE@_REF_L1=("4.5(L2)")|_REF_L6=("5.5(L4/L7)" "4.4(L5/L7)")|Type="SE"|_REF_L3=("5.5(L2/L5)" "4.4(L2/L4)")|_REF_L4=("5.5(L2/L5)" "4.4(L3/L5)")|imp="45.0"|_REF_L5=("5.5(L4/L7)")|_REF_L8=("4.5(L7)") | ByImpedance:48.0_SE@_REF_L1=("4.0(L2)")|_REF_L6=("5.0(L4/L7)" "3.9(L5/L7)")|Type="SE"|_REF_L3=("3.9(L2/L4)" "5.0(L2/L5)")|_REF_L4=("3.9(L3/L5)" "5.0(L2/L5)")|imp="48.0"|_REF_L5=("5.0(L4/L7)")|_REF_L8=("4.0(L7)") | ByImpedance:50.0_DP@_REF_L1=("10.5/4.0(L2)")|_REF_L6=("10.5/4.0(L5/L7)" "13.0/4.0(L4/L7)")|Type="DP"|_REF_L3=("13.0/4.0(L2/L5)" "10.5/4.0(L2/L4)")|_REF_L4=("10.5/4.0(L3/L5)" "13.0/4.0(L2/L5)")|imp="50.0"|_REF_L5=("13.0/4.0(L4/L7)")|_REF_L8=("10.5/4.0(L7)") | ByImpedance:50.0_SE@_REF_L1=("3.5(L2)")|_REF_L6=("4.5(L4/L7)" "3.5(L5/L7)")|Type="SE"|_REF_L3=("3.5(L2/L4)" "4.5(L2/L5)")|_REF_L4=("3.5(L3/L5)" "4.5(L2/L5)")|imp="50.0"|_REF_L5=("4.5(L4/L7)")|_REF_L8=("3.5(L7)") | ByImpedance:55.0_SE@_REF_L6=("3.51(L4/L7)")|Type="SE"|_REF_L3=("3.51(L2/L5)")|_REF_L4=("3.51(L2/L5)")|imp="55.0"|_REF_L5=("3.51(L4/L7)") | ByImpedance:68.0_DP@_REF_L1=("6.5/5.0(L2)")|_REF_L6=("7.0/4.0(L4/L7)" "6.5/5.0(L5/L7)")|Type="DP"|_REF_L3=("6.5/5.0(L2/L4)" "7.0/4.0(L2/L5)")|_REF_L4=("7.0/4.0(L2/L5)" "6.5/5.0(L3/L5)")|imp="68.0"|_REF_L5=("7.0/4.0(L4/L7)")|_REF_L8=("6.5/5.0(L7)") | ByImpedance:70.0_DP@_REF_L1=("6.0/5.0(L2)")|_REF_L6=("6.5/4.0(L4/L7)" "6.0/5.0(L5/L7)")|Type="DP"|_REF_L3=("6.0/5.0(L2/L4)" "6.5/4.0(L2/L5)")|_REF_L4=("6.0/5.0(L3/L5)" "6.5/4.0(L2/L5)")|imp="70.0"|_REF_L5=("6.5/4.0(L4/L7)")|_REF_L8=("6.0/5.0(L7)") | ByImpedance:72.0_DP@_REF_L2=("4.0/5.0(L1/L3)")|_REF_L1=("5.5/5.0(L2)")|_REF_L6=("5.4/4.0(L5/L7)" "6.0/4.0(L4/L7)")|Type="DP"|_REF_L3=("5.4/4.0(L2/L4)" "6.0/4.0(L2/L5)")|_REF_L4=("5.4/4.0(L3/L5)" "6.0/4.0(L2/L5)")|imp="72.0"|_REF_L5=("6.0/4.0(L4/L7)")|_REF_L8=("5.5/5.0(L7)") | ByImpedance:75.0_DP@_REF_L1=("5.0/5.0(L2)")|_REF_L6=("5.0/4.0(L5/L7)" "5.5/4.0(L4/L7)")|Type="DP"|_REF_L3=("5.5/4.0(L2/L5)" "5.0/4.0(L2/L4)")|_REF_L4=("5.5/4.0(L2/L5)" "5.0/4.0(L3/L5)")|imp="75.0"|_REF_L5=("5.5/4.0(L4/L7)")|_REF_L8=("5.0/5.0(L7)") | ByImpedance:80.0_DP@_REF_L1=("5.0/7.0(L2)" "4.5/5.0(L2)")|_REF_L6=("4.4/4.5(L5/L7)" "4.5/4.0(L4/L7)")|Type="DP"|_REF_L3=("4.5/4.0(L2/L5)" "4.4/4.5(L2/L4)")|_REF_L4=("4.5/4.0(L2/L5)" "4.4/4.5(L3/L5)")|imp="80.0"|_REF_L5=("4.5/4.0(L4/L7)")|_REF_L8=("4.5/5.0(L7)" "5.0/7.0(L7)") | ByImpedance:83.0_DP@_REF_L1=("3.5/4.0(L2)")|_REF_L6=("4.0/4.5(L5/L7)" "4.5/4.5(L4/L7)")|Type="DP"|_REF_L3=("4.0/4.5(L2/L4)" "4.5/4.5(L2/L5)")|_REF_L4=("4.0/4.5(L3/L5)" "4.5/4.5(L2/L5)")|imp="83.0"|_REF_L5=("4.5/4.5(L4/L7)")|_REF_L8=("3.5/4.0(L7)") | ByImpedance:85.0_DP@_REF_L2=("3.0/7.0(L1/L3)")|_REF_L1=("9.0/4.0(L3)" "4.0/5.0(L2)")|_REF_L6=("4.0/4.0(L4/L7)" "3.5/4.0(L5/L7)")|Type="DP"|_REF_L3=("3.5/4.0(L2/L4)" "4.0/4.0(L2/L5)")|_REF_L4=("3.5/4.0(L3/L5)" "4.0/4.0(L2/L5)")|imp="85.0"|_REF_L5=("4.0/4.0(L4/L7)")|_REF_L8=("9.0/4.0(L6)" "4.0/5.0(L7)") | ByImpedance:90.0_DP@_REF_L1=("4.0/8.0(L2)" "7.5/4.0(L3)")|_REF_L6=("3.5/5.0(L5/L7)" "3.5/4.5(L4/L7)")|Type="DP"|_REF_L3=("3.5/5.0(L2/L4)" "3.5/4.5(L2/L5)")|_REF_L4=("3.5/4.5(L2/L5)" "3.5/5.0(L3/L5)")|imp="90.0"|_REF_L5=("3.5/4.5(L4/L7)")|_REF_L8=("7.5/4.0(L6)" "4.0/8.0(L7)") | ByImpedance:95.0_DP@_REF_L1=("6.0/4.0(L3)" "3.5/9.0(L2)")|_REF_L6=("3.5/8.0(L5/L7)" "3.5/5.5(L4/L7)")|Type="DP"|_REF_L3=("3.5/8.0(L2/L4)" "3.5/5.5(L2/L5)")|_REF_L4=("3.5/5.5(L2/L5)" "3.5/8.0(L3/L5)")|imp="95.0"|_REF_L5=("3.5/5.5(L4/L7)")|_REF_L8=("3.5/9.0(L7)" "6.0/4.0(L6)") | LayerIndex:nil | Source:8-1.0-15k.xls | artWorks:("_REF_L4" "_REF_L6" "_REF_L5" "_REF_L3" "_REF_L8" "_REF_L1" "_REF_L2") | gtImpOutlineUsed:BOARD GEOMETRY/PANEL_OUTLINE
User.30: Board Accuracy Check,Jul 09 14:39:49 2018,Passed | Dummy-Static-No Shape On Layer Check,Jul 09 14:39:51 2018,Passed | Split Plane Check,Jul 09 14:39:49 2018,Passed
User.39: This gerber is just for your reference to find the DP impedance traces in layer L1. | DP IMPEDANCE TABLE: L1 | * - Denotes that this Impedance | is NOT used | IMP(Ohm) | *50.0 | *68.0 | *70.0 | *72.0 | *75.0 | *80.0 | *83.0 | *85.0 | 85.0 | *90.0 | *95.0 | *100.0 | 100.0 | WIDTH(mils) | 10.5/4.0 | 6.5/5.0 | 6.0/5.0 | 5.5/5.0 | 5.0/5.0 | 5.0/7.0 | 4.5/5.0 | 3.5/4.0 | 9.0/4.0 | 4.0/5.0 | 4.0/8.0 | 7.5/4.0 | 6.0/4.0 | 3.5/9.0 | 5.0/4.0 | 3.0/9.0 | TYPE | DP | Ref. Plane | L2 | L3
User.41: This gerber is just for your reference to find the SE impedance traces in layer L1. | SE IMPEDANCE TABLE: L1 | * - Denotes that this Impedance | is NOT used | IMP(Ohm) | *27.4 | *33.0 | *35.0 | *37.5 | *39.0 | 40.0 | *42.0 | *45.0 | *48.0 | 50.0 | WIDTH(mils) | 11.0 | 8.0 | 7.5 | 6.5 | 6.0 | 5.5 | 5.0 | 4.5 | 4.0 | 3.5 | TYPE | SE | Ref. Plane | L2
User.43: This gerber is just for your reference to find the DP impedance traces in layer L2. | DP IMPEDANCE TABLE: L2 | * - Denotes that this Impedance | is NOT used | IMP(Ohm) | *72.0 | *85.0 | WIDTH(mils) | 4.0/5.0 | 3.0/7.0 | TYPE | DP | Ref. Plane | L1/L3
User.45: Note:Refer to DRILL layer for ELLIPSE drill direction | FIGURE | SIZE | 10.0 | 16.0 | 22.0 | 113.0 | 150.0 | 174.0 | 178.0 | 182.0 | 197.0 | 32.0 | 38.0 | 46.0 | 65.0 | 71.0 | 86.0 | 99.0 | 119.0 | 158.0 | 58.0x24.0 | 63.0x24.0 | 63.0x36.0 | DRILL CHART: TOP to BOTTOM | ALL UNITS ARE IN MILS | PLATED | NON-PLATED | QTY | 4201 | 12 | 542 | 19 | 1 | 4 | 3 | 2 | This gerber is just for your reference to find the DP impedance traces in layer L3. | This gerber is just for your reference to find the DP impedance traces in layer L4. | This gerber is just for your reference to find the DP impedance traces in layer L5. | This gerber is just for your reference to find the DP impedance traces in layer L6. | This gerber is just for your reference to find the DP impedance traces in layer L8. | This gerber is just for your reference to find the SE impedance traces in layer L2. | This gerber is just for your reference to find the SE impedance traces in layer L3. | This gerber is just for your reference to find the SE impedance traces in layer L4. | This gerber is just for your reference to find the SE impedance traces in layer L5. | This gerber is just for your reference to find the SE impedance traces in layer L6. | This gerber is just for your reference to find the SE impedance traces in layer L8. | DP IMPEDANCE TABLE: L3 | DP IMPEDANCE TABLE: L4 | DP IMPEDANCE TABLE: L5 | DP IMPEDANCE TABLE: L6 | DP IMPEDANCE TABLE: L8 | SE IMPEDANCE TABLE: L2 | SE IMPEDANCE TABLE: L3 | SE IMPEDANCE TABLE: L4 | SE IMPEDANCE TABLE: L5 | SE IMPEDANCE TABLE: L6 | SE IMPEDANCE TABLE: L8 | * - Denotes that this Impedance | is NOT used | Model | Rogue one 13 8L | PCB_NO | 17925 | VER. | Layer | DRILL | L1 | L2SGND | L3SGND | L4SGND | TMASK | TPLACE | TSILK | TSMD | Designer | BARLEN LIU | IMP(Ohm) | *27.4 | *50.0 | 40.0 | *33.0 | *68.0 | *35.0 | *70.0 | *37.5 | *72.0 | *39.0 | *75.0 | *40.0 | *80.0 | *42.0 | *83.0 | 72.0 | *45.0 | *85.0 | *48.0 | *90.0 | *95.0 | 50.0 | 85.0 | *100.0 | *55.0 | 100.0 | Date | 07/09/2018 | WIDTH(mils) | 11.0 | 3.5 | 8.0 | 7.5 | 6.5 | 6.0 | 5.5 | 5.0 | 4.5 | 4.0 | 10.5 | 13.5 | 8.1 | 9.0 | 7.1 | 7.0 | 6.6 | 6.1 | 3.51 | 5.6 | 5.1 | 4.4 | 3.9 | 10.5/4.0 | 6.5/5.0 | 6.0/5.0 | 5.5/5.0 | 5.0/5.0 | 4.5/5.0 | 5.0/7.0 | 3.5/4.0 | 9.0/4.0 | 4.0/5.0 | 7.5/4.0 | 4.0/8.0 | 3.5/9.0 | 6.0/4.0 | 3.0/9.0 | 5.0/4.0 | 13.0/4.0 | 7.0/4.0 | 6.5/4.0 | 5.5/4.0 | 4.5/4.0 | 4.5/4.5 | 5.4/4.0 | 4.0/4.0 | 3.5/4.5 | 3.5/5.5 | 3.5/7.0 | 4.4/4.5 | 4.0/4.5 | 3.5/5.0 | 3.5/8.0 | 3.0/7.5 | TYPE | SE | DP | Ref. Plane | L1/L3 | L7 | L2/L5 | L4/L7 | L5/L7 | L2/L4 | L3/L5 | L6 | BMASK | BPLACE | BSILK | BSMD | L5GND | L7GND | L8
